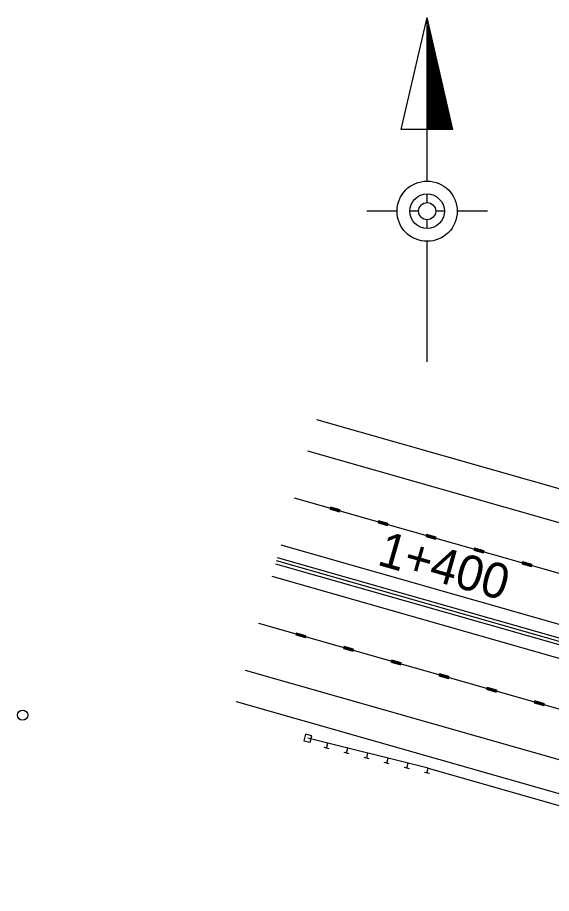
# Model space of a CAD drawing. Extents: x 3831399 to 3833095, y 499014 to 500202.
# Drawn here: x 3832621.9 to 3832674.1, y 499660.1 to 499745.8 of the extents above; entities that cross this region are included whole.
import ezdxf

# ---------------------------------------------------------------- set-up
doc = ezdxf.new("R2010")
doc.units = 0
for name, color, linetype in [('Default', 7, 'Continuous'), ('Level 15', 7, 'Continuous'), ('Level 26', 7, 'Continuous'), ('Level 27', 7, 'Continuous'), ('Level 36', 7, 'Continuous'), ('Level 48', 7, 'Continuous'), ('Level 53', 7, 'Continuous')]:
    doc.layers.add(name, color=color, linetype=linetype)

msp = doc.modelspace()

# ---------------------------------------------------------------- linework, layer by layer
at = {"layer": 'Default'}
msp.add_circle((3832622.383, 499677.569), 0.502, dxfattribs=at)
at = {"layer": 'Level 26'}
for p, q in [((3832651.141, 499706.5), (3832702.584, 499691.841)), ((3832650.267, 499703.432), (3832726.015, 499681.848)), ((3832647.645, 499694.231), (3832723.791, 499672.534)), ((3832647.295, 499693.004), (3832723.494, 499671.292)), ((3832647.121, 499692.392), (3832723.346, 499670.672)), ((3832646.771, 499691.164), (3832723.05, 499669.43)), ((3832644.149, 499681.963), (3832720.826, 499660.115)), ((3832643.275, 499678.896), (3832708.241, 499660.384))]:
    msp.add_line(p, q, dxfattribs=at)
at = {"layer": 'Level 27'}
for p, q in [((3832662.079, 499672.394), (3832650.285, 499675.309)), ((3832652.128, 499674.33), (3832652.25, 499674.822)), ((3832652.374, 499674.271), (3832651.882, 499674.392)), ((3832654.341, 499673.784), (3832653.849, 499673.905)), ((3832654.095, 499673.845), (3832654.216, 499674.337)), ((3832656.06, 499673.359), (3832656.181, 499673.85)), ((3832656.306, 499673.299), (3832655.814, 499673.42)), ((3832658.272, 499672.812), (3832657.78, 499672.934)), ((3832658.026, 499672.874), (3832658.147, 499673.365)), ((3832660.237, 499672.327), (3832659.747, 499672.449)), ((3832659.993, 499672.387), (3832660.114, 499672.879)), ((3832661.954, 499671.902), (3832662.076, 499672.394)), ((3832662.079, 499672.394), (3832701.989, 499660.93)), ((3832662.2, 499671.842), (3832661.709, 499671.964))]:
    msp.add_line(p, q, dxfattribs=at)
msp.add_lwpolyline([(3832650.512, 499674.908), (3832650.674, 499675.554), (3832650.075, 499675.7), (3832649.916, 499675.057)], close=True, dxfattribs=at)
at = {"layer": 'Level 36'}
msp.add_line((3832647.208, 499692.698), (3832723.421, 499670.983), dxfattribs=at)
at = {"layer": 'Level 48'}
for p, q in [((3832648.956, 499698.832), (3832724.902, 499677.191)), ((3832652.525, 499697.915), (3832652.474, 499697.728)), ((3832652.539, 499697.888), (3832652.498, 499697.742)), ((3832653.466, 499697.65), (3832652.525, 499697.915)), ((3832652.555, 499697.863), (3832652.525, 499697.758)), ((3832653.439, 499697.634), (3832652.539, 499697.888)), ((3832652.568, 499697.839), (3832652.548, 499697.771)), ((3832652.548, 499697.771), (3832653.371, 499697.537)), ((3832653.412, 499697.618), (3832652.555, 499697.863)), ((3832652.579, 499697.821), (3832652.566, 499697.78)), ((3832652.566, 499697.78), (3832653.358, 499697.555)), ((3832653.389, 499697.607), (3832652.568, 499697.839)), ((3832653.371, 499697.596), (3832652.579, 499697.821)), ((3832652.588, 499697.805), (3832652.584, 499697.789)), ((3832652.584, 499697.789), (3832653.349, 499697.571)), ((3832653.356, 499697.587), (3832652.588, 499697.805)), ((3832652.474, 499697.728), (3832653.412, 499697.461)), ((3832652.498, 499697.742), (3832653.398, 499697.485)), ((3832652.525, 499697.758), (3832653.383, 499697.512)), ((3832653.349, 499697.571), (3832653.356, 499697.587)), ((3832653.358, 499697.555), (3832653.371, 499697.596)), ((3832653.371, 499697.537), (3832653.389, 499697.607)), ((3832653.383, 499697.512), (3832653.412, 499697.618)), ((3832653.398, 499697.485), (3832653.439, 499697.634)), ((3832653.412, 499697.461), (3832653.466, 499697.65)), ((3832657.221, 499696.579), (3832657.167, 499696.39)), ((3832657.167, 499696.39), (3832658.105, 499696.122)), ((3832657.235, 499696.552), (3832657.194, 499696.405)), ((3832657.194, 499696.405), (3832658.092, 499696.149)), ((3832658.159, 499696.309), (3832657.221, 499696.579)), ((3832657.25, 499696.525), (3832657.221, 499696.419)), ((3832657.221, 499696.419), (3832658.076, 499696.176)), ((3832658.135, 499696.297), (3832657.235, 499696.552)), ((3832657.262, 499696.502), (3832657.241, 499696.43)), ((3832657.241, 499696.43), (3832658.065, 499696.201)), ((3832658.108, 499696.282), (3832657.25, 499696.525)), ((3832657.273, 499696.484), (3832657.259, 499696.444)), ((3832657.259, 499696.444), (3832658.056, 499696.216)), ((3832658.083, 499696.268), (3832657.262, 499696.502)), ((3832658.067, 499696.259), (3832657.273, 499696.484)), ((3832657.282, 499696.468), (3832657.277, 499696.45)), ((3832657.277, 499696.45), (3832658.045, 499696.232)), ((3832658.049, 499696.248), (3832657.282, 499696.468)), ((3832658.045, 499696.232), (3832658.049, 499696.248)), ((3832658.056, 499696.216), (3832658.067, 499696.259)), ((3832658.065, 499696.201), (3832658.083, 499696.268)), ((3832658.076, 499696.176), (3832658.108, 499696.282)), ((3832658.092, 499696.149), (3832658.135, 499696.297)), ((3832658.105, 499696.122), (3832658.159, 499696.309)), ((3832661.917, 499695.242), (3832661.863, 499695.053)), ((3832661.93, 499695.215), (3832661.888, 499695.067)), ((3832662.853, 499694.972), (3832661.917, 499695.242)), ((3832662.826, 499694.959), (3832661.93, 499695.215)), ((3832661.863, 499695.053), (3832662.801, 499694.785)), ((3832661.888, 499695.067), (3832662.785, 499694.81)), ((3832661.944, 499695.188), (3832661.915, 499695.082)), ((3832661.915, 499695.082), (3832662.772, 499694.837)), ((3832661.957, 499695.166), (3832661.937, 499695.094)), ((3832661.937, 499695.094), (3832662.758, 499694.86)), ((3832662.801, 499694.943), (3832661.944, 499695.188)), ((3832662.781, 499694.932), (3832661.957, 499695.166)), ((3832661.969, 499695.148), (3832661.957, 499695.105)), ((3832661.957, 499695.105), (3832662.747, 499694.878)), ((3832662.761, 499694.923), (3832661.969, 499695.148)), ((3832661.975, 499695.132), (3832661.973, 499695.114)), ((3832661.973, 499695.114), (3832662.74, 499694.896)), ((3832662.745, 499694.911), (3832661.975, 499695.132)), ((3832662.74, 499694.896), (3832662.745, 499694.911)), ((3832662.747, 499694.878), (3832662.761, 499694.923)), ((3832662.758, 499694.86), (3832662.781, 499694.932)), ((3832662.772, 499694.837), (3832662.801, 499694.943)), ((3832662.785, 499694.81), (3832662.826, 499694.959)), ((3832662.801, 499694.785), (3832662.853, 499694.972)), ((3832666.61, 499693.903), (3832666.556, 499693.717)), ((3832666.556, 499693.717), (3832667.495, 499693.449)), ((3832666.624, 499693.879), (3832666.581, 499693.73)), ((3832666.581, 499693.73), (3832667.479, 499693.474)), ((3832666.64, 499693.852), (3832666.608, 499693.744)), ((3832666.608, 499693.744), (3832667.465, 499693.501)), ((3832667.549, 499693.636), (3832666.61, 499693.903)), ((3832667.524, 499693.622), (3832666.624, 499693.879)), ((3832666.651, 499693.827), (3832666.631, 499693.757)), ((3832666.631, 499693.757), (3832667.454, 499693.523)), ((3832667.497, 499693.606), (3832666.64, 499693.852)), ((3832666.66, 499693.809), (3832666.649, 499693.768)), ((3832666.649, 499693.768), (3832667.443, 499693.541)), ((3832667.472, 499693.593), (3832666.651, 499693.827)), ((3832667.456, 499693.582), (3832666.66, 499693.809)), ((3832666.671, 499693.791), (3832666.667, 499693.775)), ((3832666.667, 499693.775), (3832667.434, 499693.559)), ((3832667.438, 499693.573), (3832666.671, 499693.791)), ((3832667.434, 499693.559), (3832667.438, 499693.573)), ((3832667.443, 499693.541), (3832667.456, 499693.582)), ((3832667.454, 499693.523), (3832667.472, 499693.593)), ((3832667.465, 499693.501), (3832667.497, 499693.606)), ((3832667.479, 499693.474), (3832667.524, 499693.622)), ((3832667.495, 499693.449), (3832667.549, 499693.636)), ((3832671.304, 499692.565), (3832671.25, 499692.378)), ((3832671.25, 499692.378), (3832672.19, 499692.11)), ((3832671.317, 499692.54), (3832671.277, 499692.394)), ((3832671.277, 499692.394), (3832672.177, 499692.137)), ((3832672.244, 499692.297), (3832671.304, 499692.565)), ((3832671.333, 499692.513), (3832671.304, 499692.407)), ((3832671.304, 499692.407), (3832672.161, 499692.164)), ((3832672.217, 499692.283), (3832671.317, 499692.54)), ((3832671.347, 499692.49), (3832671.326, 499692.418)), ((3832671.326, 499692.418), (3832672.148, 499692.184)), ((3832672.19, 499692.27), (3832671.333, 499692.513)), ((3832671.358, 499692.472), (3832671.344, 499692.43)), ((3832671.344, 499692.43), (3832672.136, 499692.202)), ((3832672.168, 499692.256), (3832671.347, 499692.49)), ((3832672.15, 499692.245), (3832671.358, 499692.472)), ((3832671.365, 499692.454), (3832671.36, 499692.439)), ((3832671.36, 499692.439), (3832672.127, 499692.218)), ((3832672.132, 499692.236), (3832671.365, 499692.454)), ((3832672.127, 499692.218), (3832672.132, 499692.236)), ((3832672.136, 499692.202), (3832672.15, 499692.245)), ((3832672.148, 499692.184), (3832672.168, 499692.256)), ((3832672.161, 499692.164), (3832672.19, 499692.27)), ((3832672.177, 499692.137), (3832672.217, 499692.283)), ((3832672.19, 499692.11), (3832672.244, 499692.297)), ((3832645.46, 499686.564), (3832721.938, 499664.772)), ((3832649.182, 499685.603), (3832649.128, 499685.419)), ((3832649.128, 499685.419), (3832650.062, 499685.151)), ((3832649.195, 499685.578), (3832649.153, 499685.432)), ((3832649.153, 499685.432), (3832650.048, 499685.176)), ((3832649.211, 499685.551), (3832649.18, 499685.446)), ((3832649.18, 499685.446), (3832650.032, 499685.203)), ((3832650.116, 499685.338), (3832649.182, 499685.603)), ((3832650.089, 499685.324), (3832649.195, 499685.578)), ((3832649.222, 499685.529), (3832649.204, 499685.459)), ((3832649.204, 499685.459), (3832650.021, 499685.227)), ((3832650.062, 499685.311), (3832649.211, 499685.551)), ((3832649.231, 499685.511), (3832649.22, 499685.468)), ((3832649.22, 499685.468), (3832650.01, 499685.243)), ((3832650.041, 499685.297), (3832649.222, 499685.529)), ((3832650.023, 499685.286), (3832649.231, 499685.511)), ((3832649.24, 499685.495), (3832649.238, 499685.479)), ((3832649.238, 499685.479), (3832650.001, 499685.261)), ((3832650.005, 499685.279), (3832649.24, 499685.495)), ((3832650.001, 499685.261), (3832650.005, 499685.279)), ((3832650.01, 499685.243), (3832650.023, 499685.286)), ((3832650.021, 499685.227), (3832650.041, 499685.297)), ((3832650.032, 499685.203), (3832650.062, 499685.311)), ((3832650.048, 499685.176), (3832650.089, 499685.324)), ((3832650.062, 499685.151), (3832650.116, 499685.338)), ((3832653.848, 499684.276), (3832653.794, 499684.087)), ((3832653.794, 499684.087), (3832654.728, 499683.821)), ((3832653.862, 499684.249), (3832653.821, 499684.102)), ((3832653.821, 499684.102), (3832654.712, 499683.848)), ((3832654.782, 499684.01), (3832653.848, 499684.276)), ((3832653.875, 499684.222), (3832653.848, 499684.118)), ((3832653.848, 499684.118), (3832654.699, 499683.875)), ((3832654.755, 499683.994), (3832653.862, 499684.249)), ((3832653.889, 499684.199), (3832653.871, 499684.129)), ((3832653.871, 499684.129), (3832654.685, 499683.895)), ((3832654.728, 499683.979), (3832653.875, 499684.222)), ((3832654.708, 499683.967), (3832653.889, 499684.199)), ((3832653.9, 499684.181), (3832653.889, 499684.141)), ((3832653.889, 499684.141), (3832654.676, 499683.916)), ((3832654.69, 499683.958), (3832653.9, 499684.181)), ((3832653.909, 499684.165), (3832653.902, 499684.15)), ((3832653.902, 499684.15), (3832654.667, 499683.931)), ((3832654.672, 499683.947), (3832653.909, 499684.165)), ((3832654.667, 499683.931), (3832654.672, 499683.947)), ((3832654.676, 499683.916), (3832654.69, 499683.958)), ((3832654.685, 499683.895), (3832654.708, 499683.967)), ((3832654.699, 499683.875), (3832654.728, 499683.979)), ((3832654.712, 499683.848), (3832654.755, 499683.994)), ((3832654.728, 499683.821), (3832654.782, 499684.01)), ((3832658.515, 499682.944), (3832658.461, 499682.759)), ((3832658.461, 499682.759), (3832659.395, 499682.491)), ((3832658.528, 499682.919), (3832658.488, 499682.773)), ((3832658.488, 499682.773), (3832659.381, 499682.516)), ((3832659.446, 499682.678), (3832658.515, 499682.944)), ((3832658.544, 499682.894), (3832658.515, 499682.786)), ((3832658.515, 499682.786), (3832659.365, 499682.543)), ((3832659.424, 499682.665), (3832658.528, 499682.919)), ((3832658.555, 499682.869), (3832658.535, 499682.8)), ((3832658.535, 499682.8), (3832659.352, 499682.568)), ((3832659.397, 499682.651), (3832658.544, 499682.894)), ((3832659.372, 499682.638), (3832658.555, 499682.869)), ((3832658.569, 499682.851), (3832658.555, 499682.809)), ((3832658.555, 499682.809), (3832659.343, 499682.586)), ((3832659.354, 499682.626), (3832658.569, 499682.851)), ((3832658.576, 499682.836), (3832658.571, 499682.818)), ((3832658.571, 499682.818), (3832659.336, 499682.602)), ((3832659.338, 499682.617), (3832658.576, 499682.836)), ((3832659.336, 499682.602), (3832659.338, 499682.617)), ((3832659.343, 499682.586), (3832659.354, 499682.626)), ((3832659.352, 499682.568), (3832659.372, 499682.638)), ((3832659.365, 499682.543), (3832659.397, 499682.651)), ((3832659.381, 499682.516), (3832659.424, 499682.665)), ((3832659.395, 499682.491), (3832659.446, 499682.678)), ((3832663.181, 499681.616), (3832663.13, 499681.429)), ((3832663.197, 499681.589), (3832663.154, 499681.443)), ((3832664.115, 499681.348), (3832663.181, 499681.616)), ((3832663.213, 499681.562), (3832663.181, 499681.459)), ((3832664.09, 499681.335), (3832663.197, 499681.589)), ((3832663.224, 499681.54), (3832663.204, 499681.47)), ((3832664.063, 499681.321), (3832663.213, 499681.562)), ((3832663.233, 499681.524), (3832663.222, 499681.479)), ((3832664.041, 499681.308), (3832663.224, 499681.54)), ((3832664.023, 499681.297), (3832663.233, 499681.524)), ((3832663.242, 499681.506), (3832663.24, 499681.49)), ((3832663.24, 499681.49), (3832664, 499681.272)), ((3832664.005, 499681.288), (3832663.242, 499681.506)), ((3832663.13, 499681.429), (3832664.063, 499681.162)), ((3832663.154, 499681.443), (3832664.048, 499681.189)), ((3832663.181, 499681.459), (3832664.034, 499681.216)), ((3832663.204, 499681.47), (3832664.021, 499681.236)), ((3832663.222, 499681.479), (3832664.009, 499681.256)), ((3832664, 499681.272), (3832664.005, 499681.288)), ((3832664.009, 499681.256), (3832664.023, 499681.297)), ((3832664.021, 499681.236), (3832664.041, 499681.308)), ((3832664.034, 499681.216), (3832664.063, 499681.321)), ((3832664.048, 499681.189), (3832664.09, 499681.335)), ((3832664.063, 499681.162), (3832664.115, 499681.348)), ((3832667.848, 499680.284), (3832667.794, 499680.097)), ((3832667.794, 499680.097), (3832668.728, 499679.832)), ((3832667.864, 499680.259), (3832667.821, 499680.113)), ((3832667.821, 499680.113), (3832668.714, 499679.857)), ((3832668.782, 499680.019), (3832667.848, 499680.284)), ((3832667.879, 499680.232), (3832667.848, 499680.127)), ((3832667.848, 499680.127), (3832668.698, 499679.884)), ((3832668.755, 499680.005), (3832667.864, 499680.259)), ((3832667.888, 499680.21), (3832667.87, 499680.14)), ((3832667.87, 499680.14), (3832668.687, 499679.906)), ((3832668.73, 499679.989), (3832667.879, 499680.232)), ((3832668.707, 499679.978), (3832667.888, 499680.21)), ((3832667.9, 499680.192), (3832667.888, 499680.151)), ((3832667.888, 499680.151), (3832668.678, 499679.924)), ((3832668.689, 499679.967), (3832667.9, 499680.192)), ((3832667.911, 499680.176), (3832667.904, 499680.16)), ((3832667.904, 499680.16), (3832668.667, 499679.942)), ((3832668.671, 499679.958), (3832667.911, 499680.176)), ((3832668.667, 499679.942), (3832668.671, 499679.958)), ((3832668.678, 499679.924), (3832668.689, 499679.967)), ((3832668.687, 499679.906), (3832668.707, 499679.978)), ((3832668.698, 499679.884), (3832668.73, 499679.989)), ((3832668.714, 499679.857), (3832668.755, 499680.005)), ((3832668.728, 499679.832), (3832668.782, 499680.019)), ((3832672.517, 499678.954), (3832672.463, 499678.77)), ((3832672.528, 499678.93), (3832672.487, 499678.783)), ((3832673.45, 499678.689), (3832672.517, 499678.954)), ((3832673.423, 499678.678), (3832672.528, 499678.93)), ((3832672.463, 499678.77), (3832673.396, 499678.502)), ((3832672.487, 499678.783), (3832673.381, 499678.529)), ((3832672.544, 499678.903), (3832672.514, 499678.797)), ((3832672.514, 499678.797), (3832673.367, 499678.556)), ((3832672.557, 499678.88), (3832672.537, 499678.81)), ((3832672.537, 499678.81), (3832673.356, 499678.579)), ((3832673.396, 499678.662), (3832672.544, 499678.903)), ((3832672.568, 499678.862), (3832672.555, 499678.819)), ((3832672.555, 499678.819), (3832673.345, 499678.597)), ((3832673.374, 499678.648), (3832672.557, 499678.88)), ((3832673.356, 499678.637), (3832672.568, 499678.862)), ((3832672.577, 499678.844), (3832672.573, 499678.828)), ((3832672.573, 499678.828), (3832673.336, 499678.612)), ((3832673.34, 499678.628), (3832672.577, 499678.844)), ((3832673.336, 499678.612), (3832673.34, 499678.628)), ((3832673.345, 499678.597), (3832673.356, 499678.637)), ((3832673.356, 499678.579), (3832673.374, 499678.648)), ((3832673.367, 499678.556), (3832673.396, 499678.662)), ((3832673.381, 499678.529), (3832673.423, 499678.678)), ((3832673.396, 499678.502), (3832673.45, 499678.689))]:
    msp.add_line(p, q, dxfattribs=at)
at = {"layer": 'Level 53'}
for p, q in [((3832659.446, 499734.889), (3832661.973, 499745.84)), ((3832664.5, 499734.889), (3832661.973, 499745.84)), ((3832661.973, 499729.84), (3832661.973, 499745.84)), ((3832664.5, 499734.889), (3832659.446, 499734.889)), ((3832661.973, 499727.734), (3832661.973, 499728.569)), ((3832659.023, 499726.886), (3832656.076, 499726.886)), ((3832661.154, 499726.886), (3832660.303, 499726.886)), ((3832661.973, 499726.886), (3832661.973, 499726.886)), ((3832663.671, 499726.886), (3832662.794, 499726.886)), ((3832667.87, 499726.886), (3832664.907, 499726.886)), ((3832661.973, 499725.219), (3832661.973, 499726.051)), ((3832661.973, 499712.144), (3832661.973, 499723.93))]:
    msp.add_line(p, q, dxfattribs=at)
msp.add_lwpolyline([(3832662.099, 499745.066), (3832662.099, 499734.957), (3832664.373, 499734.957), (3832662.225, 499744.56), (3832662.225, 499735.083), (3832664.248, 499735.083), (3832662.351, 499743.55), (3832662.351, 499735.209), (3832664.121, 499735.209), (3832662.479, 499742.663), (3832662.479, 499735.335), (3832663.993, 499735.335), (3832662.605, 499741.653), (3832662.605, 499735.461), (3832663.867, 499735.461), (3832662.731, 499740.769), (3832662.731, 499735.589), (3832663.741, 499735.589), (3832662.857, 499739.758), (3832662.857, 499735.715), (3832663.615, 499735.715), (3832662.983, 499738.874), (3832662.983, 499735.841), (3832663.489, 499735.841), (3832663.109, 499737.862), (3832663.109, 499735.967), (3832663.363, 499735.967), (3832663.237, 499736.725), (3832663.237, 499736.093), (3832662.099, 499734.957), (3832662.099, 499745.066), (3832663.237, 499736.725), (3832663.237, 499736.093), (3832664.373, 499734.957)], dxfattribs=at)
for radius in [2.948, 1.685, 0.842]:
    msp.add_circle((3832661.975, 499726.887), radius, dxfattribs=at)

# ---------------------------------------------------------------- texts
at = {"layer": 'Level 15'}
msp.add_text('1+400', height=3.4448, rotation=344.09531, dxfattribs=at).set_placement((3832656.97, 499692.314))

doc.saveas('drawing.dxf')
